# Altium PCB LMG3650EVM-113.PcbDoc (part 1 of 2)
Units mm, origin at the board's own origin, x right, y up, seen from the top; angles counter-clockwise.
Board outline 76.61 x 43.92 mm, 4 copper layers (Top Layer, Signal Layer 1, Signal Layer 2, Bottom Layer), stack 0.688 mm thick; 100 components, 58 nets, 255 pads, 761 vias.
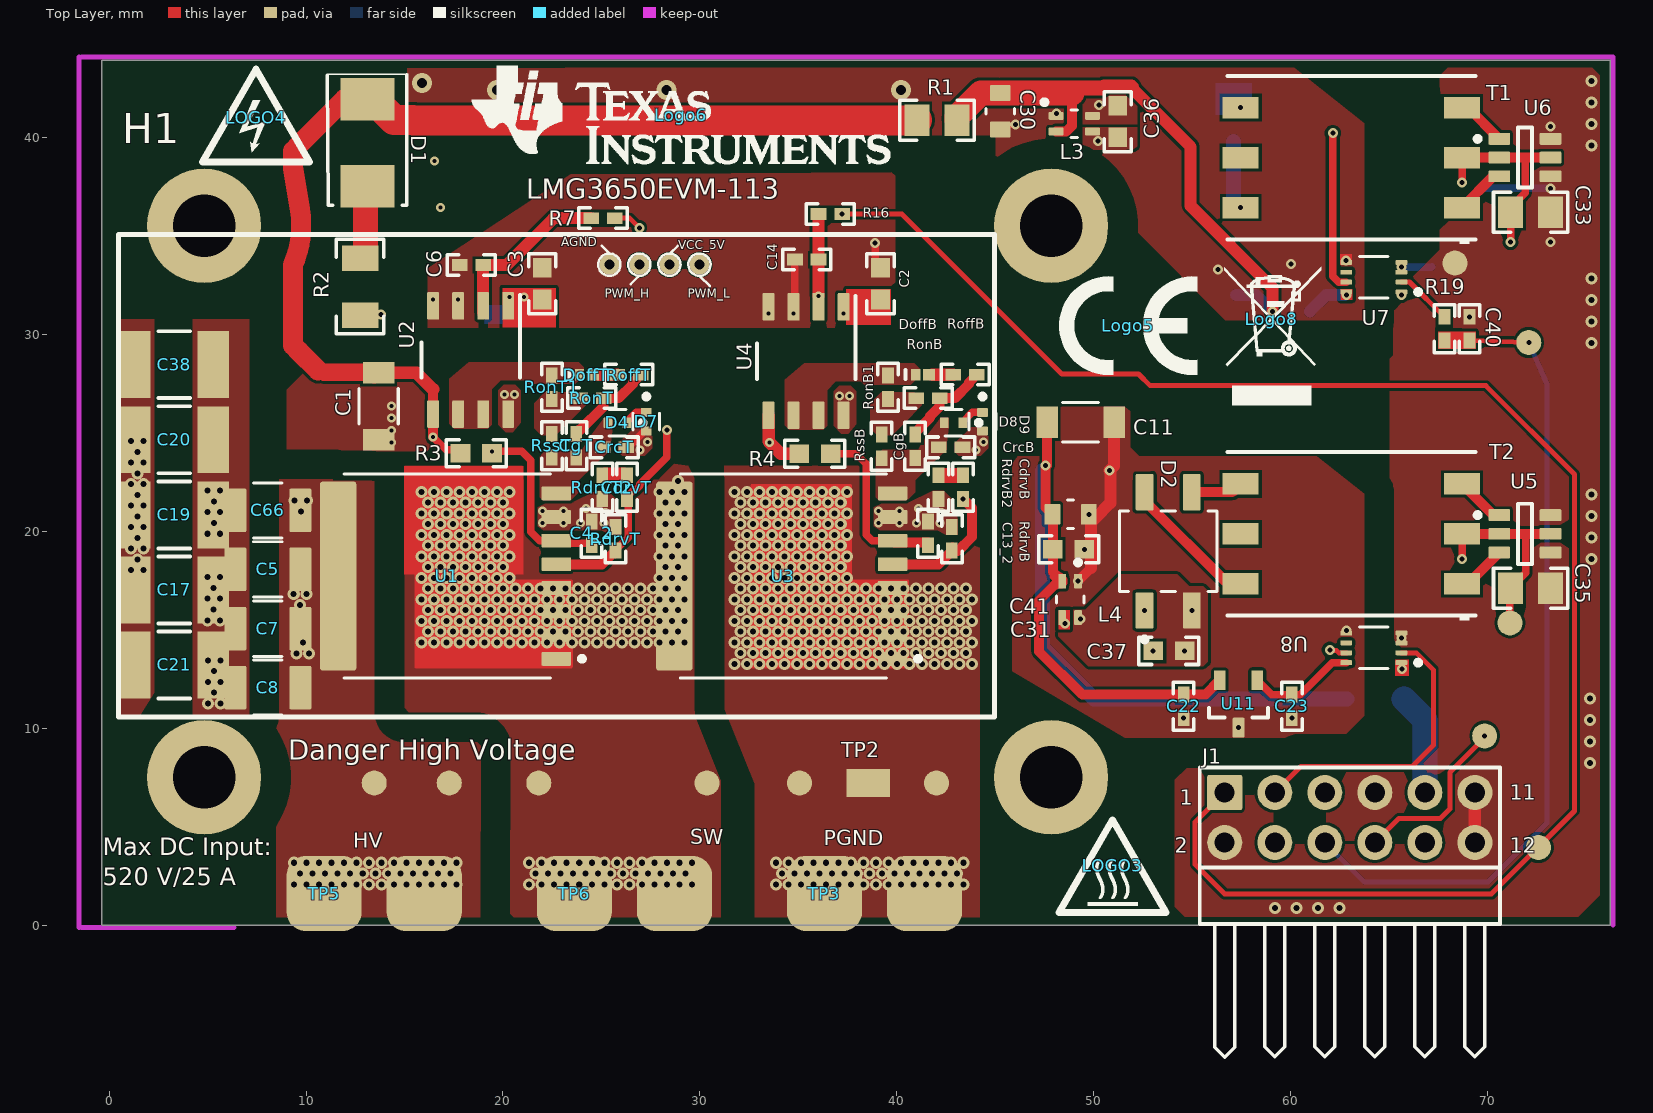
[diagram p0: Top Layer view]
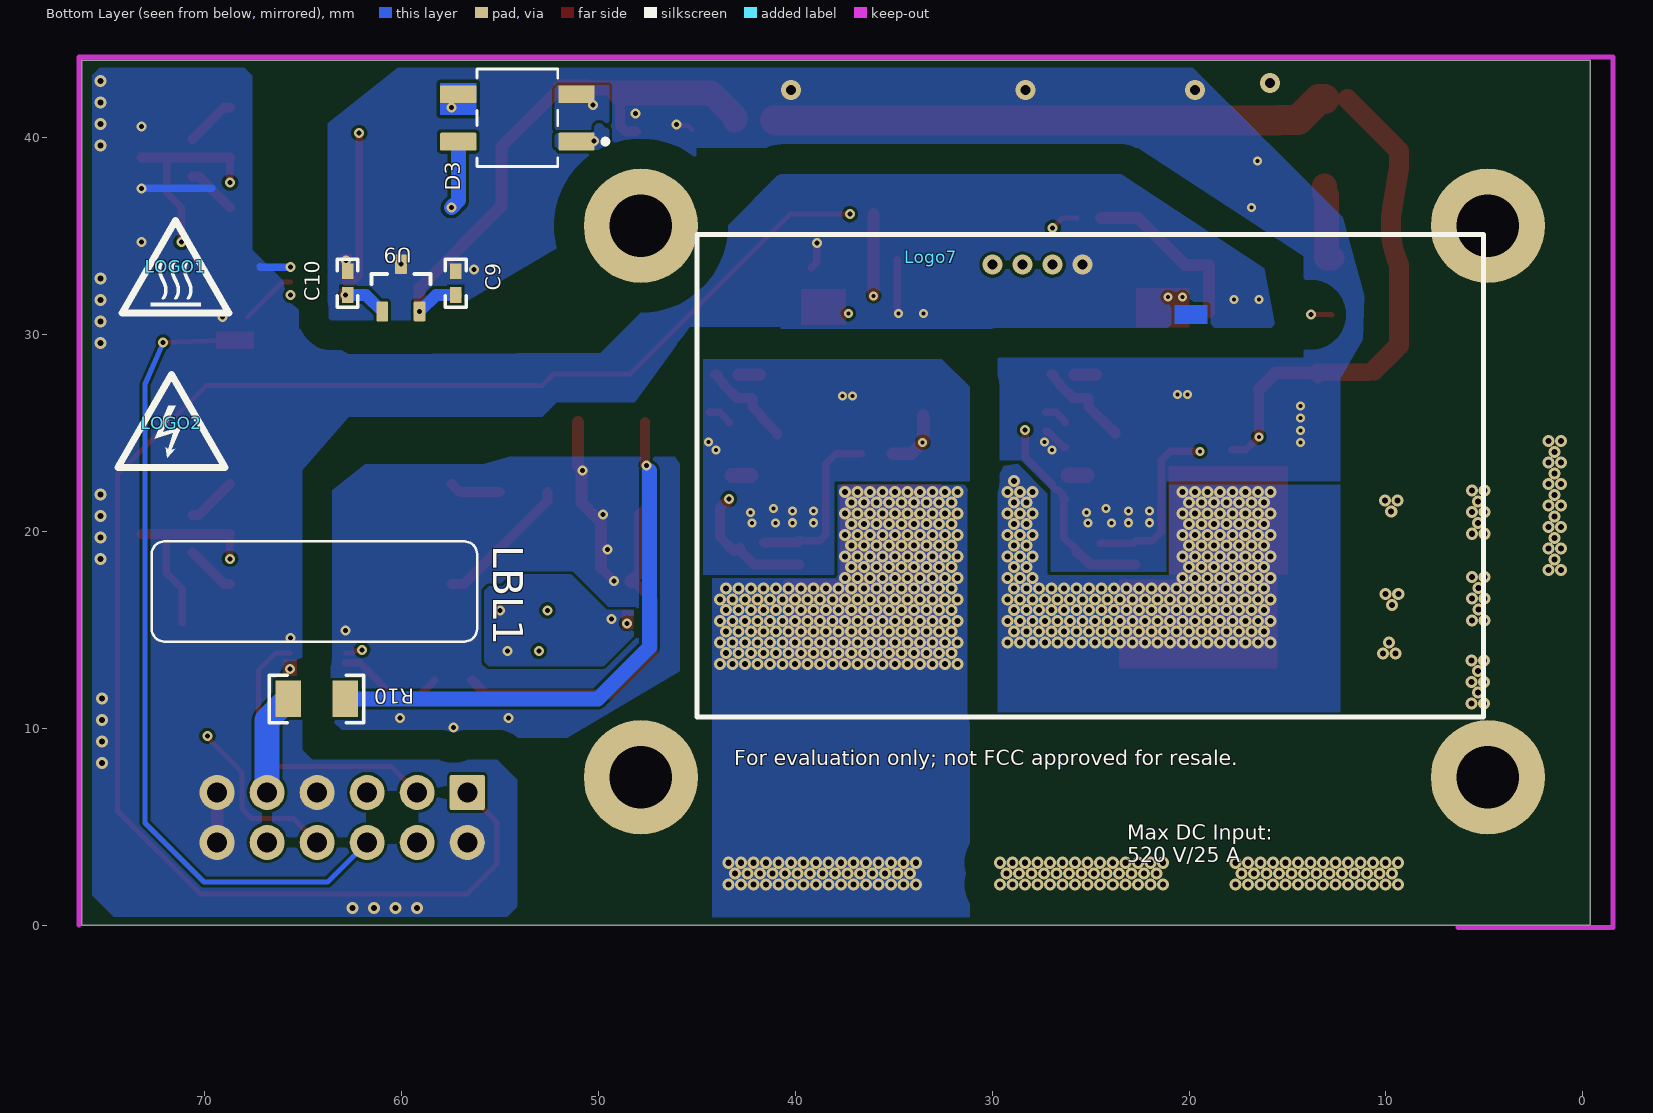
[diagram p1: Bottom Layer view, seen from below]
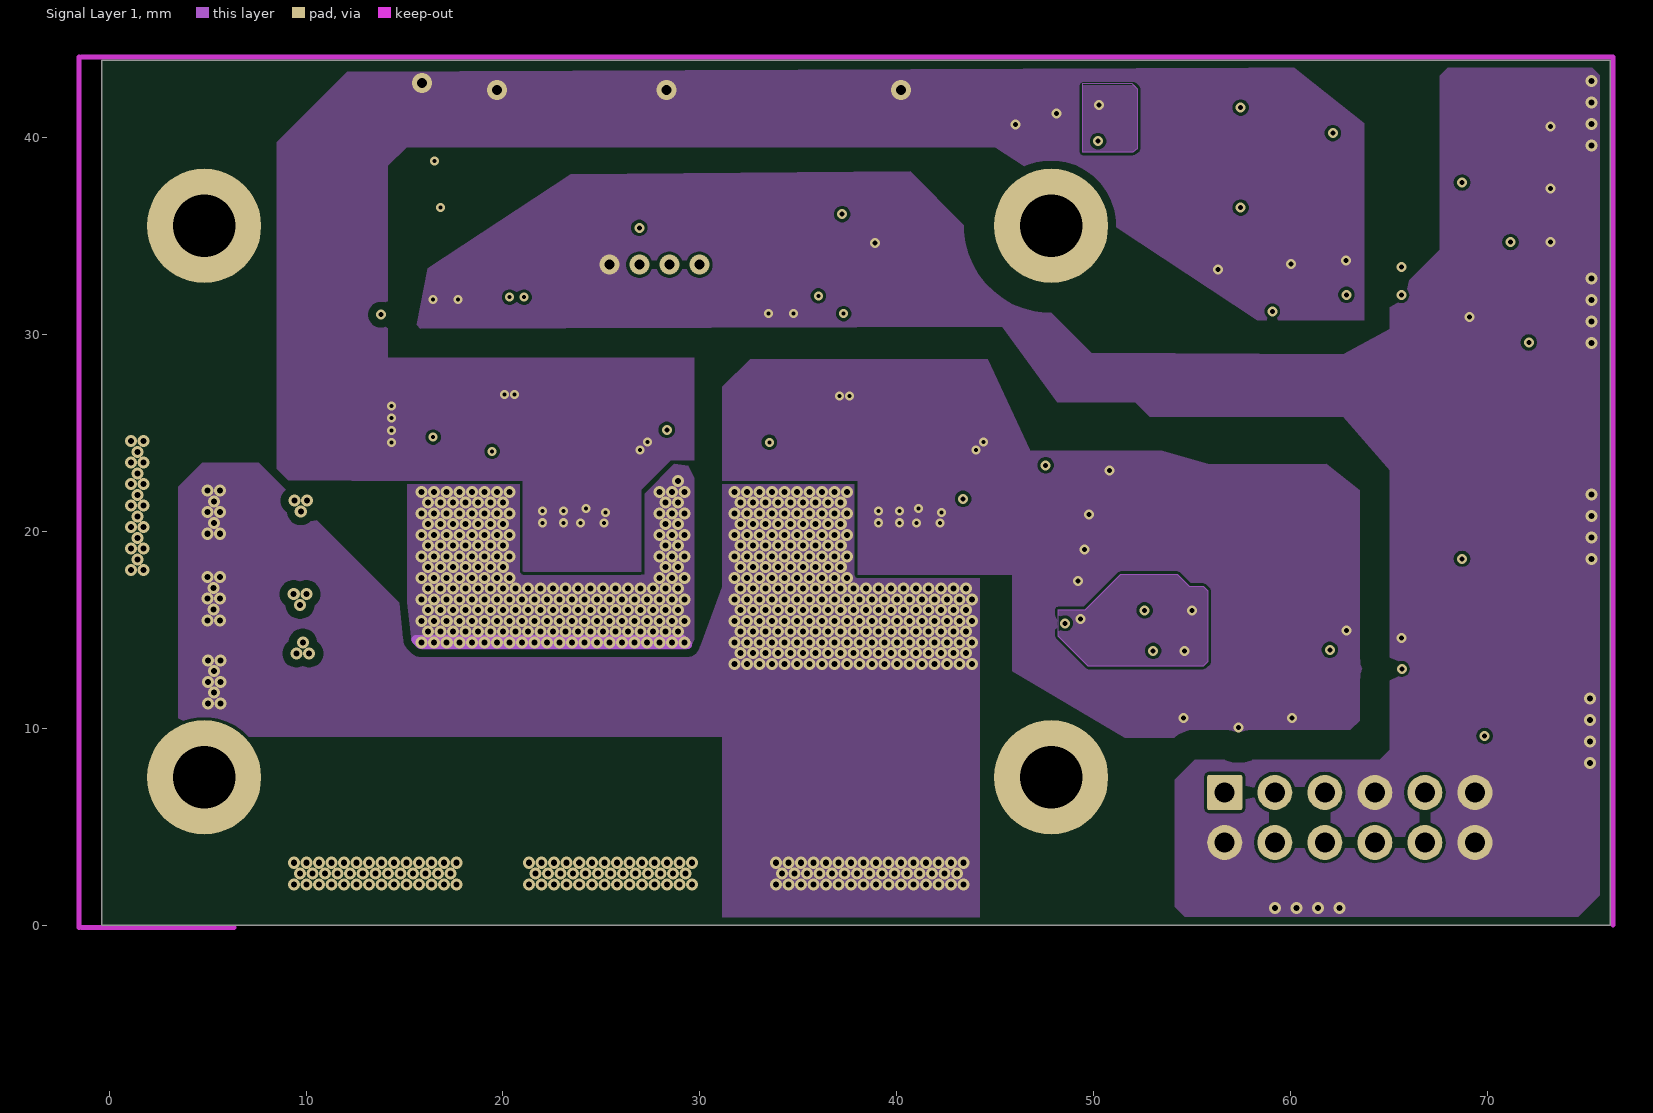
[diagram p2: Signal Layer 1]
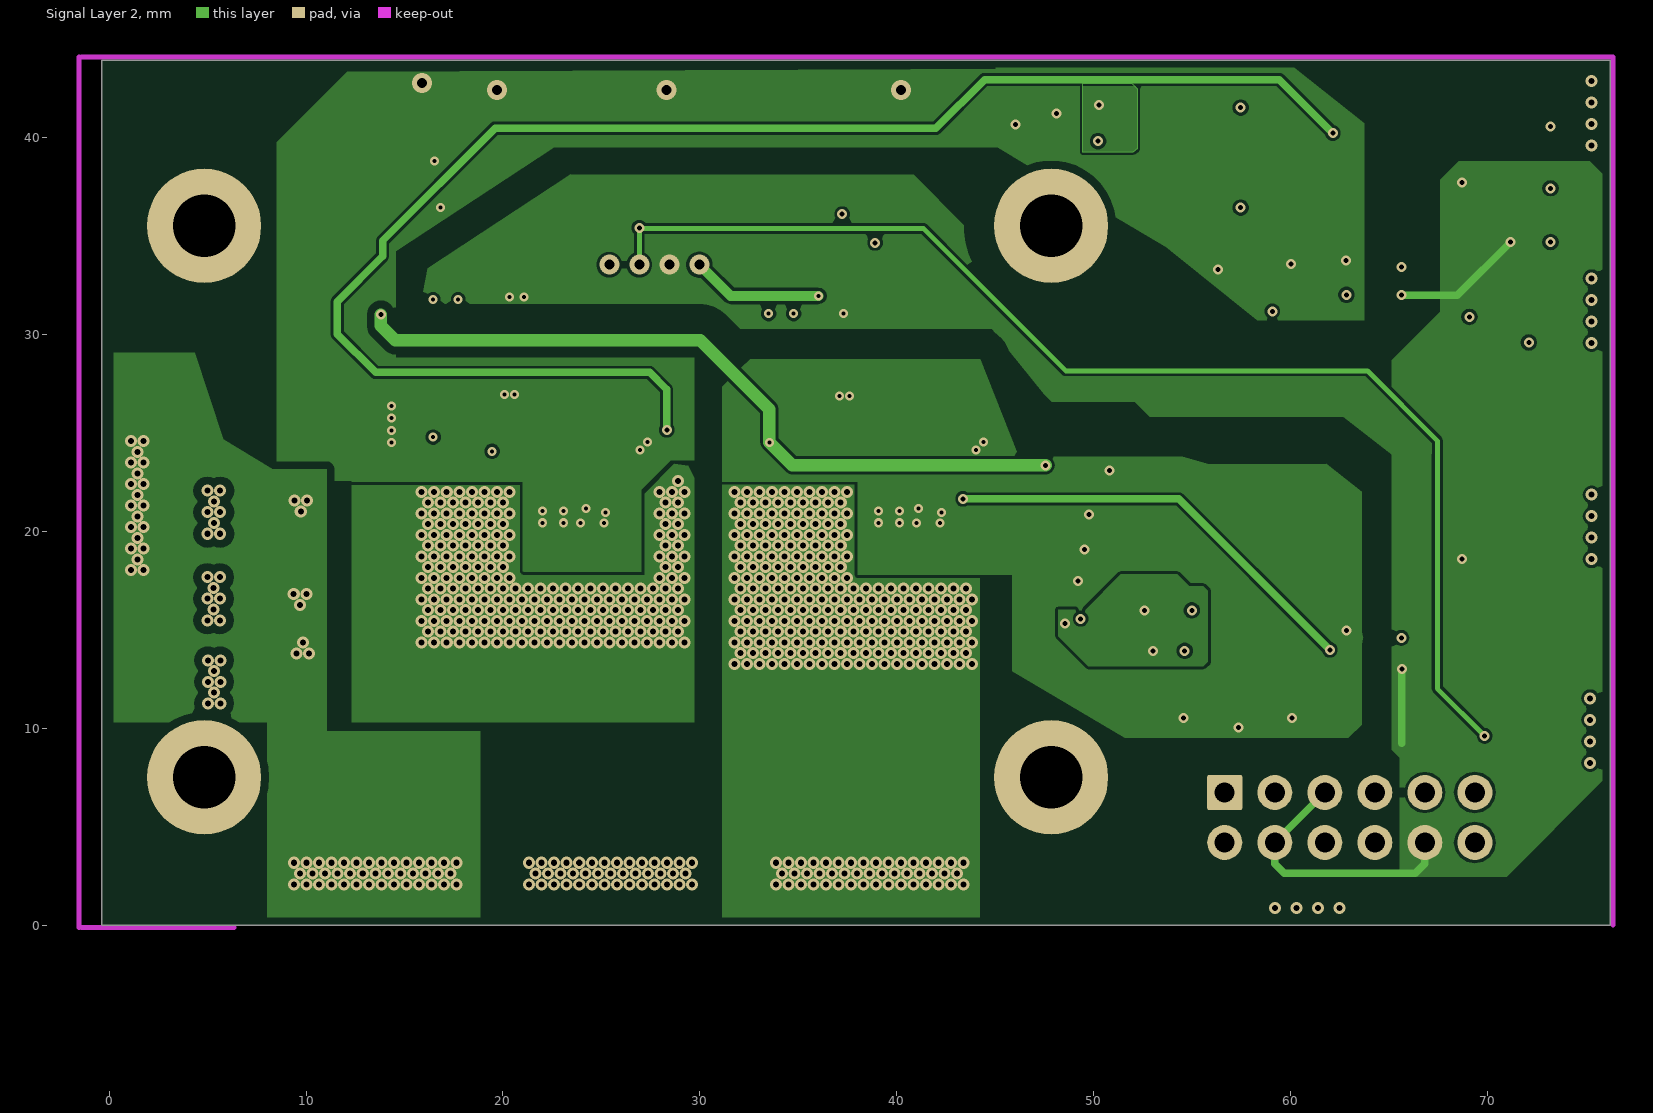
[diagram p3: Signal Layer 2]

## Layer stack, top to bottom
Top Solder: solder mask 0.0102, Solder Resist, Dk 3.5
Top Layer: signal copper 0.0711
Dielectric 1: prepreg 0.1168, FR-4, Dk 4.2
Signal Layer 1: signal copper 0.0711
Dielectric 2: core 0.17, FR-4, Dk 4.2
Signal Layer 2: signal copper 0.0711
Dielectric 3: prepreg 0.1168, FR-4, Dk 4.2
Bottom Layer: signal copper 0.0711
Bottom Solder: solder mask 0.0102, Solder Resist, Dk 3.5

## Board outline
-0.381,0 76.225,0 76.225,43.917 -0.381,43.917

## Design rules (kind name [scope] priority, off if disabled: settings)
AcuteAngle [All] p1: minimum=4.50000000000000E+0001 checktracksonly=FALSE
AssemblyTestPointUsage [All] p1: valid=2
BoardOutlineClearance [OnCopper] p1: gap=0.381 ignorepadtopadclearanceinfootprint=FALSE
Clearance Clearance_U7_6 [InNet('NC') vs InNet('S_SW')] p1: gap=0.152 ignorepadtopadclearanceinfootprint=TRUE
Clearance Clearance_Top_FET_FLT_1 [InNet('Top_FET_FLT') vs InNet('S_SW')] p2: gap=0.152 ignorepadtopadclearanceinfootprint=TRUE
Clearance Clearance_ThermalVias_2 [InNet('NC2')] p3: gap=0.508 ignorepadtopadclearanceinfootprint=TRUE
Clearance "Clearance_Thermal Vias" [InNet('NC5')] p4: gap=0.508 ignorepadtopadclearanceinfootprint=TRUE
Clearance "Clearance_Thermal Vias_1" [InNet('NC6')] p5: gap=0.508 ignorepadtopadclearanceinfootprint=TRUE
Clearance Clearance_VSW_Mid1 [(OnMultiLayer Or OnMid) And InNetClass('VSWNET') vs OnMid And Not InNetClass('VSWNET')] p6: gap=0.406 ignorepadtopadclearanceinfootprint=TRUE
Clearance Clearance_Screw_Top [InNetClass('Screw') vs OnLayer('Top Layer') And Not InNetClass('Screw')] p7: gap=1.524 ignorepadtopadclearanceinfootprint=TRUE
Clearance Clearance_Screw_Bottom [InNetClass('Screw') vs OnLayer('Bottom Layer') And Not InNetClass('Screw')] p8: gap=1.524 ignorepadtopadclearanceinfootprint=TRUE
Clearance Clearance_Screw_Other [InNetClass('Screw') vs Not OnLayer('Top Layer') AND Not InNetClass('Screw')] p9: gap=1.524 ignorepadtopadclearanceinfootprint=TRUE
Clearance Clearance_VSW_Mid2 [(OnMultiLayer Or OnMid) And Not InNetClass('VSWNET') vs OnMid And InNetClass('VSWNET')] p10: gap=0.406 ignorepadtopadclearanceinfootprint=TRUE
Clearance Clearance_VSW [InNetClass('VSWNET') and OnCopper vs Not InNetClass('VSWNET') and OnCopper] p11: gap=1.524 ignorepadtopadclearanceinfootprint=TRUE
Clearance Clearance_VHV_Mid1 [(OnMultiLayer Or OnMid) And InNetClass('VHV') vs OnMid And Not InNetClass('VHV')] p12: gap=0.406 ignorepadtopadclearanceinfootprint=TRUE
Clearance Clearance_VHV_Mid2 [(OnMultiLayer Or OnMid) And Not InNetClass('VHV') vs OnMid And InNetClass('VHV')] p13: gap=0.406 ignorepadtopadclearanceinfootprint=TRUE
Clearance Clearance_VHV [InNetClass('VHV') vs Not InNetClass('VHV')] p14: gap=1.524 ignorepadtopadclearanceinfootprint=TRUE
Clearance Clearance_INGND [InNetClass('INGND') and OnCopper vs Not InNetClass('INGND') and OnCopper] p15: gap=1.524 ignorepadtopadclearanceinfootprint=TRUE
Clearance [All] p16: gap=0.152 ignorepadtopadclearanceinfootprint=TRUE
ComponentClearance ComponentClearance_1 [All] p1: gap=0.025 collisioncheckmode=3 verticalgap=0.254 showdistances=FALSE
ComponentClearance ComponentClearance_Shunt [InComponentClass('Header') vs InComponentClass('Shunt')] p2: gap=0 collisioncheckmode=3 verticalgap=0 showdistances=FALSE
ComponentClearance ComponentClearance_MountingHoles_FiducialMarks [InComponentClass('Mounting Holes') vs InComponentClass('FiducialMark')] p3 off: gap=1.27 collisioncheckmode=3 verticalgap=0.254 showdistances=FALSE
ComponentClearance ComponentClearance_Logo [InComponentClass('Logo')] p4: gap=0 collisioncheckmode=3 verticalgap=0.254 showdistances=FALSE
ComponentClearance ComponentClearance_ScrewToNut [(HasFootprint('NY PMS 440 0025 PH')) vs (HasFootprint('Keystone_1902C'))] p5: gap=0.127 collisioncheckmode=3 verticalgap=0.254 showdistances=FALSE
ComponentClearance ComponentClearance_MountingHoles [InComponentClass('Mounting Holes')] p6: gap=6.35 collisioncheckmode=3 verticalgap=2540 showdistances=FALSE
ComponentClearance ComponentClearance_SmallPassives [HasFootprint('0201*') or HasFootprint('0402*') or HasFootprint('0508') or HasFootprint('0603*') or HasFootprint('0612') or HasFootprint('0805*') or HasFootprint('0815*') or HasFootprint('0830*') or HasFootprint('1206*') or HasFootprint('1210*') or HasFootprint('1808*') or HasFootprint('1812*') or HasFootprint('1825*') or HasFootprint('2010*') or HasFootprint('2220*') or HasFootprint('2225*') or HasFootprint('2512*') or HasFootprint('2728*') or HasFootprint('3518*') vs HasFootprint('0201*') or HasFootprint('0402*') or HasFootprint('0508') or HasFootprint('0603*') or HasFootprint('0612') or HasFootprint('0805*') or HasFootprint('0815*') or HasFootprint('0830*') or HasFootprint('1206*') or HasFootprint('1210*') or HasFootprint('1808*') or HasFootprint('1812*') or HasFootprint('1825*') or HasFootprint('2010*') or HasFootprint('2220*') or HasFootprint('2225*') or HasFootprint('2512*') or HasFootprint('2728*') or HasFootprint('3518*')] p7: gap=0.025 collisioncheckmode=3 verticalgap=0.254 showdistances=FALSE
ComponentClearance ComponentClearance_THtoSMT [IsThruComponent vs IsSMTComponent] p8: gap=0.254 collisioncheckmode=3 verticalgap=0.762 showdistances=FALSE
ComponentClearance ComponentClearance_THtoTH [IsThruComponent vs IsThruComponent] p9: gap=1.88 collisioncheckmode=3 verticalgap=0.762 showdistances=FALSE
ComponentClearance [All] p10: gap=0.025 collisioncheckmode=3 verticalgap=0.254 showdistances=FALSE
DiffPairsRouting [All] p1: maxlimit=2.54 minlimit=0.254 mostfreqgap=0.254 toplayer_minwidth=0.381 toplayer_maxwidth=0.381 toplayer_prefwidth=0.381 midlayer1_minwidth=0.381 midlayer1_maxwidth=0.381 midlayer1_prefwidth=0.381 midlayer2_minwidth=0.381 midlayer2_maxwidth=0.381 midlayer2_prefwidth=0.381 bottomlayer_minwidth=0.381 bottomlayer_maxwidth=0.381 bottomlayer_prefwidth=0.381 maxuncoupledlength=25.4
FabricationTestPointUsage TestPointUsage [All] p1: valid=2 allowmultiple=FALSE
FabricationTestpoint Testpoint [All] p1: side=3 testpointundercomponent=TRUE minsize=1.016 maxsize=2.54 preferedsize=1.524 minholesize=0 maxholesize=1.016 preferedholesize=0.813 testpointgrid=0.025 allowsidetop=TRUE allowsidebottom=TRUE usegrid=TRUE gridtolerance=0
FanoutControl Fanout_LCC [IsLCC] p1: bgadir=Out bgaviamode=Centered fanoutstyle=Auto fanoutdirection=Alternating viagrid=0.025 // Fanout_LCC (Default Rule)
FanoutControl Fanout_BGA [IsBGA] p2: bgadir=Out bgaviamode=Centered fanoutstyle=Auto fanoutdirection=Alternating viagrid=0.025 // Fanout_BGA (Default Rule)
HoleSize [All] p1: absolutevalues=TRUE maxlimit=6.375 minlimit=0.152 maxpercent=80.000 minpercent=20.000
MinimumAnnularRing MinimumAnnularRing_ThermalPadVias [IsVia and InAnyComponent] p1: minimumring=0.114
MinimumAnnularRing [IsVia] p2: minimumring=0.114
MinimumSolderMaskSliver MinimumSolderMaskSliver_Logo [InComponentClass('Logo') vs InComponentClass('Logo')] p1: minsoldermaskwidth=0.018
MinimumSolderMaskSliver [All] p2: minsoldermaskwidth=0.1
PlaneConnect [All] p1: planeconnectstyle=Relief reliefexpansion=0.254 reliefentries=4 reliefconductorwidth=0.254 reliefairgap=0.254
PolygonConnect [All] p1: connectstyle=Direct reliefconductorwidth=0.254 reliefentries=4 polygonreliefangle="90 Angle" airgapwidth=0.254
RoutingVias ThermalPadVias [IsVia and InAnyComponent] p1: holewidth=0.2 width=0.5 viastyle="Through Hole" minholewidth=0.2 minwidth=0.5 maxholewidth=0.33 maxwidth=0.6
RoutingVias [All] p2: holewidth=0.254 width=0.508 viastyle="Through Hole" minholewidth=0.152 minwidth=0.254 maxholewidth=1.016 maxwidth=1.651
SMDToCorner [All] p1: distance=30000
SilkToSilkClearance [All] p1: silktosilkclearance=0
SilkToSolderMaskClearance SilkscreenOverComponentPads [IsPad] p1: minsilkscreentomaskgap=0.127 clearancetoexposedcopper=TRUE
SolderMaskExpansion [All] p1: expansion=0.05 istentingtop=FALSE
SupplyNets "Schematic Supply Nets_15" [InNet('5V')] p1: voltage=0.000
SupplyNets "Schematic Supply Nets_14" [InNet('SW')] p2: voltage=0.000
SupplyNets "Schematic Supply Nets_13" [InNet('S_PGND')] p3: voltage=0.000
SupplyNets "Schematic Supply Nets_12" [InNet('ISO_12V_H')] p4: voltage=0.000
SupplyNets "Schematic Supply Nets_11" [InNet('VGG_H')] p5: voltage=0.000
SupplyNets "Schematic Supply Nets_10" [InNet('PGND')] p6: voltage=0.000
SupplyNets "Schematic Supply Nets_9" [InNet('12V')] p7: voltage=0.000
SupplyNets "Schematic Supply Nets_8" [InNet('5V_B')] p8: voltage=0.000
SupplyNets "Schematic Supply Nets_7" [InNet('ISO_12V_L')] p9: voltage=0.000
SupplyNets "Schematic Supply Nets_6" [InNet('5V_T')] p10: voltage=0.000
SupplyNets "Schematic Supply Nets_5" [InNet('NC')] p11: voltage=0.000
SupplyNets "Schematic Supply Nets_4" [InNet('AGND')] p12: voltage=0.000
SupplyNets "Schematic Supply Nets_3" [InNet('ISO_12V_L_B')] p13: voltage=0.000
SupplyNets "Schematic Supply Nets_2" [InNet('S_SW')] p14: voltage=0.000
SupplyNets "Schematic Supply Nets_1" [InNet('ISO_12V_H_B')] p15: voltage=0.000
SupplyNets "Schematic Supply Nets" [InNet('HVBUS')] p16: voltage=0.000
Width [All] p1: maxlimit=25.4 minlimit=0.152 preferedwidth=0.254 checkconnectedcopper=TRUE
18 further rules are at their usual default settings.

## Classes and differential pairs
component class Logo: Logo6
component class Label: LBL1
component class Header: J1
component class AssemblyNote: ZZ1 ZZ2 ZZ3 ZZ4
net class Screw: NC1 NC2 NC3 NC4
net class PGND: 5V_B 12V Bot_FET_FLT IN_L ISO_12V_L ISO_12V_L_B ISO_RET_L_B ISONC2 NetC13_2_1 NetCdrvB_1 NetCgB_1 NetD1_2 NetD2_3 NetD2_4 NetD8_1 NetDoffB_1 NetDoffB_2 NetRonB1_2 PGND S_PGND
net class INGND: 5V 12V AGND Bot_FET_FAULT Bot_FET_PWM NetR19_1 NetT1_1 NetT1_3 NetT2_1 NetT2_3 PWM_H PWM_L Top_FET_FAULT Top_FET_PWM
component class HVP113A1_Hardware: !PCB1 FID2 H1 H3 H4 H5 H6 LBL1 LOGO1 LOGO2 LOGO3 LOGO4 Logo5 Logo6 Logo7 Logo8 ZZ1 ZZ2 ZZ3 ZZ4
component class HVP113A1_BlankSheet: 33 C1 C2 C3 C4_2 C5 C6 C7 C8 C9 C10 C11 C13_2 C14 C17 C19 C20 C21 C22 C23 C30 C31 C33 C35 C36 C37 C38 C40 C41 C66 CdrvB CdrvT CgB CgT CrcB CrcT D1 D2 D3 D4 D7 D8 D9 DoffB DoffT HV J1 L3 L4 PGND R1 R2 R3 R4 R7 R10 R16 R19 RdrvB RdrvB2 RdrvT RdrvT2 RoffB RoffT RonB RonB1 RonT RonT1 RssB RssT SW T1 T2 TP2 TP3 TP5 TP6 U1 U2 U3 U4 U5 U6 U7 U8 U9 U11
net class VSWNET: 5V_T IN_H ISO_12V_H ISO_12V_H_B ISO_RET_H_B ISONC3 NC NetC4_2_1 NetCdrvT_1 NetCgT_1 NetD3_3 NetD3_4 NetD4_1 NetDoffT_1 NetDoffT_2 NetRonT1_2 S_SW SW Top_FET_FLT VGG_H
net class VHV: HVBUS

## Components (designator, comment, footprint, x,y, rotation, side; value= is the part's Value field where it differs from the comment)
C1 "TMK316AB7106KLHT" 1206_180 13.691,26.338 r270 top value=10uF
C2 "GRM188R70J104KA01D" 0603 39.167,32.563 r90 top value=0.1uF
C3 "GRM188R70J104KA01D" 0603 21.996,32.563 r90 top value=0.1uF
C4_2 "C1005X7R1H104K050BB" 0402 24.506,19.888 r90 top value=0.1uF
C5 "CGA6M1C0G3A682J200AE" FP-CGA6M1C0G3A682J200AE_1210-MFG 8.067,18.061 r0 top value=6.8nF
C6 "C1005C0G1H680J050BA" 0402 18.399,33.51 r180 top value=68pF
C7 "CGA6M1C0G3A682J200AE" FP-CGA6M1C0G3A682J200AE_1210-MFG 8.067,15.045 r0 top value=6.8nF
C8 "CGA6M1C0G3A682J200AE" FP-CGA6M1C0G3A682J200AE_1210-MFG 8.067,12.055 r0 top value=6.8nF
C9 "C1005X7R1H104K050BB" 0402 57.226,32.588 r90 bottom value=0.1uF
C10 "C1005X7R1H104K050BB" 0402 62.713,32.588 r90 bottom value=0.1uF
C11 "TMK316AB7106KLHT" 1206_180 49.327,25.527 r180 top value=10uF
C13_2 "C1005X7R1H104K050BB" 0402 41.573,19.888 r90 top value=0.1uF
C14 "C1005C0G1H680J050BA" 0402 35.422,33.782 r0 top value=68pF
C17 "C1812C303KDGLCAUTO" 1812_254 3.302,17.018 r0 top value=0.03uF
C19 "C1812C303KDGLCAUTO" 1812_254 3.302,20.828 r0 top value=0.03uF
C20 "C1812C303KDGLCAUTO" 1812_254 3.302,24.638 r0 top value=0.03uF
C21 "C1812C303KDGLCAUTO" 1812_254 3.302,13.208 r0 top value=0.03uF
C22 "C1005X7R1H104K050BB" 0402 54.559,11.1 r270 top value=0.1uF
C23 "C1005X7R1H104K050BB" 0402 60.046,11.1 r270 top value=0.1uF
C30 "CGA4J1X7S1E106K125AC" FP-CGA4J1X7S1E106K125AC_0805-MFG 45.243,41.316 r270 top value=10µF
C31 "GRT188C81E475KE13D" 0603 48.717,19.075 r0 top value=4.7uF
C33 "GCM21BR71C475KA73L" 0805_HV 72.166,36.195 r0 top value=4.7uF
C35 "GCM21BR71C475KA73L" 0805_HV 72.166,17.094 r0 top value=4.7uF
C36 "GRT188C81E475KE13D" 0603 51.206,40.792 r90 top value=4.7uF
C37 "GRT188C81E475KE13D" 0603 53.81,13.919 r0 top value=4.7uF
C38 "C1812C303KDGLCAUTO" 1812_254 3.302,28.448 r0 top value=0.03uF
C40 "GCQ1555C1H430JB01D" 0402 69.063,30.277 r90 top value=43pF
C41 "CGA4J1X7S1E106K125AC" FP-CGA4J1X7S1E106K125AC_0805-MFG 48.819,20.853 r0 top value=10µF
C66 "CGA6M1C0G3A682J200AE" FP-CGA6M1C0G3A682J200AE_1210-MFG 8.067,21.051 r0 top value=6.8nF
CdrvB "GCM1555C1H220JA16D" 0402 43.357,22.233 r270 top value=22pF
CdrvT "GCM1555C1H220JA16D" 0402 26.289,22.233 r270 top value=22pF
CgB "GCM1555C1H220JA16D (NC)" 0402 40.926,24.309 r270 top value=22pF
CgT "GCM1555C1H220JA16D (NC)" 0402 23.724,24.333 r270 top value=22pF
CrcB "GCM1555C1H220JA16D" 0402 42.727,24.257 r180 top value=22pF
CrcT "GCM1555C1H220JA16D" 0402 25.659,24.257 r180 top value=22pF
D1 "GB01SLT06-214" SMB 13.114,39.722 r270 top value=650V
D2 "KMB24STR" FP-KMB24STR_SMD4-MFG 53.772,18.974 r90 top
D3 "KMB24STR" FP-KMB24STR_SMD4-MFG 54.099,40.976 r0 bottom
D4 "DZ9F5V6S92-7" FP-CDZVT2R5.1B_SOD-923-MFG 25.811,25.504 r180 top
D7 "DZ9F5V6S92-7" FP-CDZVT2R5.1B_SOD-923-MFG 27.277,25.554 r270 top
D8 "DZ9F5V6S92-7" FP-CDZVT2R5.1B_SOD-923-MFG 42.878,25.504 r180 top
D9 "DZ9F5V6S92-7" FP-CDZVT2R5.1B_SOD-923-MFG 44.345,25.554 r270 top
DoffB "NSR05F30NXT5G" DSN2_0402 41.325,27.94 r0 top value=30V
DoffT "NSR05F30NXT5G" DSN2_0402 24.257,27.94 r0 top value=30V
H1 "S05MZZ14A" S05MZZ14 47.826,35.5 r180 top locked
HV "3621-0-32-15-00-00-08-0" MILL-MAX_3621-0-32-XX-00-00-08-0 16.002,-0.787 r0 top
J1 "TSW-106-08-G-D-RA" AB12-DEST 62.992,5.461 r0 top
L3 "ACM2012-900-2P-T001" FP-ACM2012-900-2P-T001_SMD4-MFG 49.003,40.682 r0 top
L4 "ACM2012-900-2P-T001" FP-ACM2012-900-2P-T001_SMD4-MFG 48.793,16.535 r270 top
LBL1 "THT-14-423-10" Label_650x200 64.402,16.936 r180 bottom
LOGO1 "CAUTION HOT SURFACE" IEC_HotSurface_Small 71.45,33.426 r180 bottom
LOGO2 "DANGER HIGH VOLTAGE" IEC_HighVoltage_Small 71.653,25.476 r180 bottom
LOGO3 "CAUTION HOT SURFACE" IEC_HotSurface_Small 50.947,2.999 r0 top
LOGO4 "DANGER HIGH VOLTAGE" IEC_HighVoltage_Small 7.462,40.977 r0 top
Logo5 "CE Mark" CE_Mark_5mm 51.74,30.429 r0 top
Logo6 "Texas Instruments" TI_Stacked_Overlay_Small 29.043,41.122 r0 top
Logo7 "FCC disclaimer" FCC_disclaimer 33.096,33.909 r180 bottom
Logo8 "WEEE logo" WEEE_Minimum 59.03,30.759 r0 top
PGND "3621-0-32-15-00-00-08-0" MILL-MAX_3621-0-32-XX-00-00-08-0 41.402,-0.787 r0 top
R1 "CRCW08050000Z0EAHP" 0805_HV 42.034,40.87 r180 top value=0
R2 "CRCW12062R05FKEA" 1206 12.749,32.412 r90 top value=2.05
R3 "CRCW06030000Z0EA" 0603 18.644,23.952 r0 top value=0
R4 "CRCW06030000Z0EA" 0603 35.839,23.927 r0 top value=0
R7 "CRCW040249R9FKED" 0402 25.078,35.887 r180 top value=49.9
R10 "ERJ-8GEY0R00V" 1206 64.287,11.481 r180 bottom value=0
R16 "CRCW040249R9FKED" 0402 36.622,36.093 r180 top value=49.9
R19 "CRCW0402300RJNED" 0402 67.793,30.277 r270 top value=300
RdrvB "ERJ-2GEJ203X" 0402 42.784,19.615 r270 top value=20k
RdrvB2 "ERJ-2GEJ203X" 0402 42.11,22.233 r90 top value=20k
RdrvT "ERJ-2GEJ203X" 0402 25.716,19.615 r270 top value=20k
RdrvT2 "ERJ-2GEJ203X" 0402 25.042,22.233 r90 top value=20k
RoffB "CRCW04022R40JNED" 0402 43.458,27.94 r0 top value=2.4
RoffT "CRCW04022R40JNED" 0402 26.391,27.94 r0 top value=2.4
RonB "CRCW04029R10JNED" 0402 41.579,26.746 r0 top value=9.1
RonB1 "CRCW04029R10JNED" 0402 39.547,27.305 r270 top value=9.1
RonT "CRCW04029R10JNED" 0402 24.511,26.746 r0 top value=9.1
RonT1 "CRCW04029R10JNED" 0402 22.479,27.305 r270 top value=9.1
RssB "CRCW04029R10JNED" 0402 39.228,24.303 r270 top value=9.1
RssT "CRCW04029R10JNED" 0402 22.479,24.333 r270 top value=9.1
SW "3621-0-32-15-00-00-08-0" MILL-MAX_3621-0-32-XX-00-00-08-0 28.702,-0.787 r0 top
T1 "750315371" Wurth_750315371 63.068,38.964 r180 top value=105uH
T2 "750315371" Wurth_750315371 63.068,19.863 r180 top value=105uH
TP2 "S2751-46R" Harwin_S2751-46R 38.543,7.214 r0 top
TP3 "3621-0-32-15-00-00-08-0" MILL-MAX_3621-0-32-XX-00-00-08-0 36.322,-0.787 r0 top
TP5 "3621-0-32-15-00-00-08-0" MILL-MAX_3621-0-32-XX-00-00-08-0 10.922,-0.787 r0 top
TP6 "3621-0-32-15-00-00-08-0" MILL-MAX_3621-0-32-XX-00-00-08-0 23.622,-0.787 r0 top
U1 "LMG3650" KLA0009A-NV 17.172,17.715 r180 top
U2 "UCC5350SBDR" D0008B_HV 18.359,28.688 r270 top
U3 "LMG3650" KLA0009A-NV 34.239,17.715 r180 top
U4 "UCC5350SBDR" D0008B_HV 35.387,28.633 r270 top
U5 "SN6505BQDBVTQ1" DBV0006A-MFG 71.882,19.863 r0 top
U6 "SN6505BQDBVTQ1" DBV0006A-MFG 71.882,38.964 r0 top
U7 "ISO6521REU" REU0008A-MFG 64.211,32.893 r180 top
U8 "ISO6521REU" REU0008A-MFG 64.211,14.072 r180 top
U9 "TLV76050DBZR" DBZ0003A_N 60.01,32.353 r90 bottom
U11 "TLV76050DBZR" DBZ0003A_N 57.343,11.227 r270 top
ZZ1 "This Assembly Note is for PCB labels only" AssemblyNoteLabel 6.579,58.979 r0 top
ZZ2 "These assemblies are ESD sensitive, ESD precautions shall be observed." AssemblyNote 6.579,56.515 r0 top
ZZ3 "These assemblies must be clean and free from flux and all contaminants. Use of no clean flux is not acceptable." AssemblyNote 6.579,54.381 r0 top
ZZ4 "These assemblies must comply with workmanship standards IPC-A-610 Class 2, unless otherwise specified." AssemblyNote 6.579,52.324 r0 top

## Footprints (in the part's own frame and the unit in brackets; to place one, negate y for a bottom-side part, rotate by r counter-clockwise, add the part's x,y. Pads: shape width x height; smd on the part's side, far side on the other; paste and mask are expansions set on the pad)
0402 [mm] "0402 from SM-752 data"
  rect 0.8x0.6 smd: 1(-0.6,0) 2(0.6,0)
  silkscreen extent -1.22,-0.52 1.22,0.52, body extent -0.55,-0.3 0.55,0.3, height 0.6
0603 [mm] "0603 from SM-752 data"
  rect 1x0.95 smd: 1(-0.8,0) 2(0.8,0)
  silkscreen extent -1.52,-0.69 1.52,0.69, body extent -0.87,-0.47 0.87,0.47, height 1
0805_HV [mil] "0805 with 30mil clearance between pads"
  rect 50x63 smd: 1(-40,0) 2(40,0)
  silkscreen extent -74,-40 74,40, body extent -43,-29 43,29, height 57
1206 [mm] "1206 from SM-752 data"
  rect 1.3x1.85 smd: 1(-1.45,0) 2(1.45,0)
  silkscreen extent -2.4,-1.21 2.4,1.21, body extent -1.7,-0.9 1.7,0.9, height 1.35
1206_180 [mm] "1206_180"
  rect 1.1x1.6 smd: 1(-1.7,0) 2(1.7,0)
  silkscreen extent -0.9,-1 0.9,1, body extent -1.75,-0.95 1.75,0.95, height 1.8
1812_254 [mm] "SMD, 2-Leads, Body 4.8x3.4mm"
  rect 1.6x3.4 smd: 1(-2,0) 2(2,0)
  silkscreen extent -0.8,-1.7 0.8,1.7, body extent -2.4,-1.7 2.4,1.7, height 2.54
AB12-DEST [mil] "Samtec right angle header, pins flipped from convention"
  rrect10% 70x70 hole 40: 1(-250,50)
  round 70 hole 40: 2(-250,-50) 3(-150,50) 4(-150,-50) 5(-50,50) 6(-50,-50) 7(50,50) 8(50,-50) 9(150,50) 10(150,-50) 11(250,50) 12(250,-50)
  silkscreen extent -300,-479 300,100, body extent -300,-440 300,63, height 219
AssemblyNote [mm] "Assembly Note"
AssemblyNoteLabel [mm] "Assembly Note for PCB Labels"
CE_Mark_5mm [mm] "Minimum text height for CE Mark"
  silkscreen extent -3.5,-2.5 3.5,2.5
D0008B_HV [mm] "SOIC, 8-Leads, Body 4.9x3.9mm, Pitch 1.27mm, HV / Isolation option"
  rrect17% 1.4x0.6 smd: 1(-2.75,1.905) 2(-2.75,0.635) 3(-2.75,-0.635) 4(-2.75,-1.905) 5(2.75,-1.905) 6(2.75,-0.635) 7(2.75,0.635) 8(2.75,1.905)
  silkscreen extent -3.3,-2.5 0.9,2.5, body extent -3,-2.45 3,2.45, height 1.63
DBV0006A-MFG [mm]
  rrect17% 1.1x0.6 smd paste+0 mask+0: 1(-1.3,0.95) 2(-1.3,0) 3(-1.3,-0.95) 4(1.3,-0.95) 5(1.3,0) 6(1.3,0.95)
  silkscreen extent -2.52,-1.53 0.35,1.53, body extent -1.95,-1.78 1.95,1.78, height 0.25
DBZ0003A_N [mm] "SOT23, 3-Leads, Body 2.9x1.3mm, Pitch 0.95mm, Lead Span 2.4mm, IPC Medium Density"
  rrect17% 1x0.6 smd: 1(-1.2,0.95) 2(-1.2,-0.95) 3(1.2,0)
  silkscreen extent 0.2,-1.5 0.7,1.5, body extent -1.26,-1.46 1.26,1.46, height 0.98
DSN2_0402 [mm] "ON SEMICONDUCTOR"
  rect 0.47x0.6 smd: 1(-0.367,0)
  rect 0.6x0.6 smd: 2(0.308,0)
  silkscreen extent -0.89,-0.22 -0.89,0.25, body extent -0.5,-0.3 0.5,0.3, height 0.32
FCC_disclaimer [mm]
FP-ACM2012-900-2P-T001_SMD4-MFG [mm]
  rrect25% 0.75x0.4 smd paste+0 mask+0: 1(-0.925,0.4) 2(-0.925,-0.4) 3(0.925,-0.4) 4(0.925,0.4)
  silkscreen extent -1.64,-0.7 0.18,1.22, body extent -1.4,-0.8 1.4,0.8, height 0.25
FP-CDZVT2R5.1B_SOD-923-MFG [mm]
  rrect22% 0.45x0.55 smd paste+0 mask+0: 1(-0.475,0) 2(0.475,0)
  silkscreen extent -1.4,-0.67 0.43,0.67, body extent -0.8,-0.43 0.8,0.43, height 0.25
FP-CGA4J1X7S1E106K125AC_0805-MFG [mm]
  rrect13% 0.8x1.05 smd paste+0 mask+0: 1(-0.925,0) 2(0.925,0)
  silkscreen extent -0.15,-0.72 0.15,0.72, body extent -1.43,-0.82 1.43,0.82, height 0.25
FP-CGA6M1C0G3A682J200AE_1210-MFG [mm]
  rrect9% 1.1x2.2 smd paste+0 mask+0: 1(-1.65,0) 2(1.65,0)
  silkscreen extent -0.72,-1.4 0.72,1.4, body extent -1.6,-1.25 1.6,1.25, height 2.81
FP-KMB24STR_SMD4-MFG [mm]
  rrect11% 1.84x0.9 smd paste+0 mask+0: 1(-3,1.2) 2(-3,-1.2) 3(3,-1.2) 4(3,1.2)
  silkscreen extent -4.59,-2.47 2.05,2.47, body extent -4.02,-2.58 4.02,2.58, height 0.25
Harwin_S2751-46R [mm] "Test Point, SMT"
  rect 2.2x1.4 smd: 1(0,0)
  body extent -1,-0.6 1,0.6, height 1.4
IEC_HighVoltage_Small [mm]
  silkscreen extent -2.72,-2.24 2.72,2.47
IEC_HotSurface_Small [mm]
  silkscreen extent -2.72,-2.36 2.72,2.35
KLA0009A-NV [mm]
  rrect14% 1.5x0.7 smd paste+0 mask-1000: 1(-5.539,4.2) 2(-5.539,3) 3(-5.539,1.8) 4(-5.539,0.6) 5(-5.539,-0.6) 6(-5.539,-1.8) 7(-5.539,-3) 8(-5.539,-4.2)
  rrect15% 1.843x9.6 smd paste-1000 mask-1000: 9(5.539,0)
  Top Layer region: -6.36,4.6 -6.351,4.635 -6.325,4.661 -6.29,4.67 -6.29,4.67 1.587,4.67 1.622,4.661 1.648,4.635 1.657,4.6 1.657,4.6 1.657,-4.6 1.648,-4.635 1.622,-4.661 1.587,-4.67 1.587,-4.67 -3.388,-4.67 -3.423,-4.661 -3.449,-4.635 -3.458,-4.6 -3.458,-4.6 -3.458,0.13 -3.462,0.149 -3.473,0.165 -3.489,0.176 -3.508,0.18 -3.508,0.18 -6.29,0.18 -6.317,0.185 -6.339,0.201 -6.355,0.223 -6.36,0.25 -6.36,0.25
  silkscreen extent -6.96,-5.18 5.24,5.18, body extent -6.46,-5.1 6.56,5.1, height 0.25
Label_650x200 [mil] "Thermal Transfer Label"
  round 1 on Mech14: 0(0,0)
  silkscreen extent -325,-100 325,100, body extent -325,-100 325,100, height 1
MILL-MAX_3621-0-32-XX-00-00-08-0 [mil]
  rrect50% 150x150 smd: 1(0,94)
  body extent -62,-199 63,157, height 62
REU0008A-MFG [mm]
  rrect40% 0.6x0.25 smd paste+0 mask+0: 1(-1.4,0.75) 2(-1.4,0.25) 3(-1.4,-0.25) 4(-1.4,-0.75) 5(1.4,-0.75) 6(1.4,-0.25) 7(1.4,0.25) 8(1.4,0.75)
  silkscreen extent -2.38,-1.05 0.72,1.05, body extent -1.8,-1.15 1.8,1.15, height 0.25
S05MZZ14 [mm]
  round 5.8 hole 3.175: 1(0,28) 1(0,0) 1(43,28) 1(43,0)
  body extent -3.42,-3.33 46.31,31.37
SMB [mm] "Molded Diode, 2-Leads, Body 5.4x3.6mm, IPC Medium Density, based on OnSemi component dimensions"
  rect 2.159x2.743 smd: 1(-2.21,0) 2(2.21,0)
  silkscreen extent -3.52,-2.08 3.18,2.08, body extent -2.7,-1.8 2.7,1.8, height 2.32
TI_Stacked_Overlay_Small [mm]
  silkscreen extent -10.63,-2.49 10.63,2.49
WEEE_Minimum [mm] "WEEElie bin"
  silkscreen extent -2.42,-4.38 2.52,2.65
Wurth_750315371 [mm] "SMD, Body 12.6x8.3mm, Pitch 2.54mm"
  rect 1.83x1.09 smd: 1(-5.62,2.54) 2(-5.62,0) 3(-5.62,-2.54) 4(5.62,-2.54) 5(5.62,0) 6(5.62,2.54)
  silkscreen extent -6.3,-4.15 6.3,4.4, body extent -6.35,-4.2 6.35,4.2, height 4.11

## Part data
C1 C11: library part CMP-0750154-1, "CAP, CERM, 10 µF, 25 V,+/- 10%, X7R, AEC-Q200 Grade 1, 1206", Cap_Case=1206, Manufacturer="Taiyo Yuden", TempCo=X7R, Tolerance_%=10%, Value2=25V, ValueDisplayed=10µF
C2 C3: library part CMP-0007359-4, "CAP, CERM, 0.1 uF, 6.3 V, +/- 10%, X7R, 0603", Cap_Case=0603, Manufacturer=MuRata, Supplier Part Number 1=GRM188R70J104KA01D-ND, TempCo=X7R, Tolerance_%=10%, Value1=Unknown, Value2=6.3V, ValueDisplayed=0.1uF
C4_2 C9 C10 C13_2 C22 C23: library part CMP-0006297-2, "CAP, CERM, 0.1 uF, 50 V, +/- 10%, X7R, 0402", Cap_Case=0402, Manufacturer=TDK, Supplier Part Number 1=445-5932-1-ND, TempCo=X7R, Tolerance_%=10%, Value1="0.039064 ohm", Value2=50V, ValueDisplayed=0.1uF
C5 C7 C8 C66: library part CMP-0092736-1, "Cap Ceramic 6.8nF 1000V C0G 5% Pad SMD 1210 +125°C Automotive T/R", Manufacturer=TDK, Operating Temperature Range="-55°C to +125°C", TempCo=30ppm/°C, Temperature Characteristic=C0G, Tolerance_%=0.05%, ValueDisplayed=6.8nF
C6 C14: library part CMP-0006251-2, "CAP, CERM, 68 pF, 50 V, +/- 5%, C0G/NP0, 0402", Alternate Manufacturer=Murata, Alternate PartNumber=GRM1555C1H680JA01D, Cap_Case=0402, Manufacturer=TDK, Supplier Part Number 1=445-1245-1-ND, TempCo=C0G/NP0, Tolerance_%=5%, Value1=Unknown, Value2=50V, ValueDisplayed=68pF
C17 C19 C20 C21 C38: library part CMP-0009326-2, "0.03 µF ±10% 1000V (1kV) Ceramic Capacitor C0G, NP0 1812 (4532 Metric)", Cap_Case=1812, Manufacturer=Kemet, Supplier Part Number 1=399-C1812C303KDGLCAUTOTR-ND, TempCo=NP0, Tolerance_%=10%, Value1=Unknown, Value2=1000V, ValueDisplayed=0.03uF
C30 C41: library part CMP-0091069-1, "Cap Ceramic 10uF 25V X7S 10% Pad SMD 0805 +125°C Automotive T/R", Manufacturer="TDK Corporation", Operating Temperature Range="-55°C to +125°C", TempCo=22%, Temperature Characteristic=X7S, Tolerance_%=0.1%, ValueDisplayed=10uF
C31 C36 C37: library part CMP-0085645-1, "CAP, CERM, 4.7 µF, 25 V,+/- 10%, X6S, AEC-Q200 Grade 2, 0603", Cap_Case=0603, Manufacturer=MuRata, TempCo=X6S, Tolerance_%=10%, Value2=25V, ValueDisplayed=4.7µF
C33 C35: library part CMP-0008020-2, "CAP, CERM, 4.7 uF, 16 V, +/- 10%, X7R, AEC-Q200 Grade 1, 0805", Cap_Case=0805, Manufacturer=MuRata, Supplier Part Number 1=490-5332-1-ND, TempCo=X7R, Tolerance_%=10%, Value1=Unknown, Value2=16V, ValueDisplayed=4.7uF
C40: library part CMP-0860835-1, "CAP, CERM, 43 pF, 50 V,+/- 5%, C0G/NP0, AEC-Q200 Grade 1, 0402", Cap_Case=0402, Manufacturer=MuRata, TempCo=C0G/NP0, Tolerance_%=5%, Value2=50V, ValueDisplayed=43pF
CdrvB CdrvT CrcB CrcT: library part CMP-0006348-2, "CAP, CERM, 22 pF, 50 V, +/- 5%, C0G/NP0, AEC-Q200 Grade 1, 0402", Cap_Case=0402, Manufacturer=MuRata, Supplier Part Number 1=490-9648-1-ND, TempCo=C0G/NP0, Tolerance_%=5%, Value1=Unknown, Value2=50V, ValueDisplayed=22pF
CgB CgT: library part CMP-0006348-2, "CAP, CERM, 22 pF, 50 V, +/- 5%, C0G/NP0, AEC-Q200 Grade 1, 0402", Cap_Case=0402, Manufacturer=MuRata, PartNumber=GCM1555C1H220JA16D, Supplier Part Number 1=490-9648-1-ND, TempCo=C0G/NP0, Tolerance_%=5%, Value1=Unknown, Value2=50V, ValueDisplayed=22pF
D1: library part CMP-0076998-2, "Diode, Schottky, 650 V, 1 A, SMB", Manufacturer="GeneSiC Semiconductor", Value1=1A, Value2=2V
D2 D3: library part CMP-0090590-2, "Bridge Rectifier Single Phase Schottky 40V Surface Mount MBS", Digikey Part Number=1655-1884-1-ND, Forward Current=2A, Manufacturer="SMC Diode Solutions", Max Surge Forward Current=50A, Operating Temperature Range="-55°C to +150°C", Peak Reverse Current=0.1mA, ValueDisplayed=28pF
D4 D7 D8 D9: library part CMP-0123139-1, "DIODE ZENER 5.6V 200MW SOD923", Digikey Part Number=CDZVT2R5.1BCT-ND, Manufacturer=ROHM, Max Reverse Leakage Current=2uA, Mouser Part Number=755-CDZVT2R5.1B, Operating Temperature Range="to +150°C", Part Number=CDZVT2R5.1B, Power_W=100mW
DoffB DoffT: library part CMP-0077002-2, "Diode, Schottky, 30 V, 0.5 A, 0402 Diode", Manufacturer="ON Semiconductor", Value1=0.5A, Value2=0.43V
H1: library part HeatSink_NoPins, "Heat Sink, Black Anodized, 35 x 50 mm,  20 mm high, with Push Pin and Spring", Manufacturer="Alpha Novatech", PartNumber=S05MZZ13
HV PGND SW TP3 TP5 TP6: library part CMP-0082316-1, Manufacturer=Mill-Max, Supplier Part Number 1=575-3621032150000
J1: library part CMP-0075414-2, "Header, 100mil, 6x2, Gold, R/A, TH", Color=Black, Current_A=6.3A, Manufacturer=Samtec, Supplier Part Number 1=SAM1037-06-ND, Voltage_V=550V
L3 L4: library part CMP-0090488-1, "2 Line Common Mode Choke Surface Mount 90 Ohms @ 100MHz 400mA DCR 190mOhm", Digikey Part Number=445-15969-1-ND, Impedance At Frequency="90Ω @ 100MHz", Manufacturer=TDK, Mouser Part Number=810-ACM20129002PT001, Operating Temperature Range="-40°C to +105°C"
LBL1: library part CMP-0003625-1, "Thermal Transfer Printable Labels, 0.650\" W x 0.200\" H - 10,000 per roll", Manufacturer=Brady, Supplier Part Number 1=97C5133
LOGO1 LOGO3: library part CMP-0074837-1, "IEC 61010-1 Hot Surface Warning"
LOGO2 LOGO4: library part CMP-0074835-1, "IEC 61010-1 High Voltage Warning"
Logo5: library part CMP-0074844-1
Logo6: library part CMP-0074838-1, "Texas Instrument Corporate Signature"
Logo7: library part CMP-0074847-1, "FCC_disclaimer"
Logo8: library part CMP-0074769-1
R1: library part CMP-0020443-3, "RES, 0, 5%, 0.333 W, AEC-Q200 Grade 0, 0805", Manufacturer=Vishay-Dale, Power_W=333mW, Supplier Part Number 1=541-0.0TBCT-ND, TempCo="200 ppm/C", Tolerance_%=5%, Value2=0.333W, Value_Code=0000, ValueDisplayed=0
R2: library part CMP-0016879-3, "RES, 2.05, 1%, 0.25 W, AEC-Q200 Grade 0, 1206", Manufacturer=Vishay-Dale, Power_W=250mW, Supplier Part Number 1=541-2.05FFCT-ND, TempCo="100 ppm/C", Tolerance_%=1%, Value2=0.25W, Value_Code=2R05, ValueDisplayed=2.05
R3 R4: library part CMP-0025697-4, "RES, 0, 5%, 0.1 W, AEC-Q200 Grade 0, 0603", Manufacturer=Vishay-Dale, Power_W=100mW, Supplier Part Number 1=541-0.0GCT-ND, TempCo="200 ppm/C", Tolerance_%=5%, Value2=0.1W, Value_Code=0000, ValueDisplayed=0
R7 R16: library part CMP-0026404-2, "RES, 49.9, 1%, 0.063 W, AEC-Q200 Grade 0, 0402", Manufacturer=Vishay-Dale, Power_W=63mW, Supplier Part Number 1=541-49.9LCT-ND, TempCo="100 ppm/C", Tolerance_%=1%, Value2=0.063W, Value_Code=49R9, ValueDisplayed=49.9
R10: library part CMP-0018748-3, "RES, 0, 5%, 0.25 W, AEC-Q200 Grade 0, 1206", Manufacturer=Panasonic, Power_W=250mW, Supplier Part Number 1=P0.0ECT-ND, TempCo="600 ppm/C", Tolerance_%=5%, Value2=0.25W, Value_Code=0000, ValueDisplayed=0
R19: library part CMP-0026902-3, "RES, 300, 5%, 0.063 W, AEC-Q200 Grade 0, 0402", Manufacturer=Vishay-Dale, Power_W=63mW, Supplier Part Number 1=541-300JCT-ND, TempCo="200 ppm/C", Tolerance_%=5%, Value2=0.063W, Value_Code=300R, ValueDisplayed=300
RdrvB RdrvB2 RdrvT RdrvT2: library part CMP-0026996-1, "RES, 20 k, 5%, 0.1 W, AEC-Q200 Grade 0, 0402", Manufacturer=Panasonic, Power_W=100mW, Supplier Part Number 1=P20KJCT-ND, TempCo="200 ppm/C", Tolerance_%=5%, Value2=0.1W, Value_Code=20k0, ValueDisplayed=0
RoffB RoffT: library part CMP-0026899-2, "RES, 2.4, 5%, 0.063 W, 0402", Manufacturer=Vishay-Dale, Power_W=63mW, Supplier Part Number 1=541-2.4JCT-ND, TempCo="200 ppm/C", Tolerance_%=5%, Value2=0.063W, Value_Code=2R40
RonB RonB1 RonT RonT1 RssB RssT: library part CMP-0026991-4, "RES, 9.1, 5%, 0.063 W, AEC-Q200 Grade 0, 0402", Manufacturer=Vishay-Dale, Power_W=63mW, Supplier Part Number 1=541-9.1JCT-ND, TempCo="200 ppm/C", Tolerance_%=5%, Value2=0.063W, Value_Code=9R10
T1 T2: library part CMP-0030623-1, "Transformer, 105uH, TH", Manufacturer="Wurth Elektronik", ValueDisplayed=105uH
TP2: library part CMP-0003968-1, "Test Point, SMT", Manufacturer=Harwin, Supplier Part Number 1=952-2664-1-ND
U1 U3: library part CMP-0120607-2, Manufacturer="Texas Instruments", Operating Temperature Range=to, Part Number=LMG365x
U2 U4: library part CMP-0077706-1, "3-kVRMS Single-Channel Isolated Gate Drivers, D0008B (SOIC-8)", Alternate Manufacturer="Texas Instruments", Alternate PartNumber=UCC5350SBD
U5 U6: library part CMP-0089033-2, "Transformer Driver PMIC SOT-23-6", Manufacturer="Texas Instruments", Operating Temperature Range="-40°C to +125°C"
U7 U8: library part CMP-0035039-1, "General Purpose Dual-Channel Functional Isolators", Manufacturer="Texas Instruments", Max Supply Voltage=5.5V, Min Supply Voltage=1.71V, Nominal Supply Current=1.2-5.2mA, Operating Temperature Range="-40°C to +125°C"
U9 U11: library part CMP-0074892-1, "100-mA, 30-V, Fixed-Output, Linear-Voltage Regulator, DBZ0003A (SOT-23-3)", Alternate Manufacturer="Texas Instruments", Alternate PartNumber=TLV76050DBZT
ZZ1: library part CMP-0003616-3
ZZ2: library part CMP-0077236-1
ZZ3: library part CMP-0077237-1
ZZ4: library part CMP-0077238-1

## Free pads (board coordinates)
  round 1.27 smd paste-0.762: 1(13.462,7.214) 1(17.272,7.214) 1(21.819,7.214) 1(30.353,7.214) 1(35.052,7.214) 1(42.012,7.214) 1(68.326,33.604) 1(69.837,9.601) 1(71.12,15.342) 1(72.078,29.575) 1(72.568,3.937)

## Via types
v1: diameter 0.61, hole 0.305, Top Layer to Bottom Layer, tented both sides, 665 vias
v2: diameter 0.508, hole 0.254, Top Layer to Bottom Layer, tented both sides, 47 vias
v3: diameter 0.457, hole 0.203, Top Layer to Bottom Layer, tented both sides, 41 vias
v4: diameter 1.016, hole 0.508, Top Layer to Bottom Layer, 8 vias

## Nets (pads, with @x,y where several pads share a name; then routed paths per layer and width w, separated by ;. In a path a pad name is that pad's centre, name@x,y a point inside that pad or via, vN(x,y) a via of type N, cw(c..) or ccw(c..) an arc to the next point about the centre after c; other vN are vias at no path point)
5V: C2.1 C3.1 C33.1 C35.1 J1.4 J1.5 J1.10 pad.1@71.12,15.342 T1.2 T2.2 U2.1 U4.1 U5.2 U5.5 U6.2 U6.5 U7.1 U8.1 | length 45.2
  Top Layer w0.381: v3(37.292,31.047) U4.1@37.292,31.102 ; v2(68.688,18.593) T2.2@68.688,19.863 ; v2(68.688,37.694) T1.2@68.688,38.964 ; pad.1@71.12,15.342 71.12,17.064 C35.1@71.15,17.094 71.933,17.877 71.933,19.863 ; v2(71.15,34.671) C33.1@71.15,36.195 71.15,36.428 71.907,37.186 71.907,38.964
  Top Layer w0.508: T2.2@68.688,19.863 U5.2@70.582,19.863 71.933,19.863 U5.5@73.182,19.863 ; T1.2@68.688,38.964 U6.2@70.582,38.964 71.907,38.964 U6.5@73.182,38.964
  Signal Layer 2 w0.381: J1.5@61.722,6.731 J1.4@59.182,4.191 59.182,3.111 59.652,2.642 66.319,2.642 66.802,3.124 J1.10@66.802,4.191 ; v2(65.608,31.979) 68.458,31.979 v2(71.15,34.671) ; 65.634,9.22 v2(65.634,13.005)
  other v3: 20.34,31.877 21.073,31.877
  other v4: 28.448,33.528
5V_B: C23.1 U8.8 U11.1 | length 5.5
  Top Layer w0.381: U11.1@58.293,12.427 59.02,11.7 C23.1@60.046,11.7 60.468,11.7 62.09,13.322 U8.8@62.811,13.322
5V_T: C10.1 U7.8 U9.1 | length 2.1
  Bottom Layer w0.61: U9.1@60.96,31.153 61.795,31.988 C10.1@62.713,31.988
  other v2: 62.822,31.994
12V: J1.9 R10.1 | length 5.2
  Bottom Layer w1.27: R10.1@65.737,11.481 66.802,10.416 J1.9@66.802,6.731
AGND: C2.2 C3.2 C6.2 C14.1 C33.2 C35.2 C40.2 J1.2 J1.7 J1.11 J1.12 pad.1@68.326,33.604 U2.3 U2.4 U4.3 U4.4 U5.4 U5.6 U6.4 U6.6 U7.3 U7.4 U8.3 U8.4 | length 11.8
  Top Layer w0.381: v3(34.752,31.047) 34.822,31.117 C14.1@34.822,33.782 ; v2(38.887,34.639) 38.887,33.642 C2.2@39.167,33.363
  Top Layer w0.635: J1.12@69.342,4.191 J1.11@69.342,6.731
  Bottom Layer w0.381: v2(65.611,33.401) 67.132,33.401 67.158,33.426 ; 69.614,37.404 v2(73.182,37.404)
  other v1: 59.182,0.86 60.275,0.86 61.367,0.86 62.459,0.86 75.188,8.231 75.188,9.323 75.188,10.415 75.188,11.508 75.268,18.58 75.268,19.672 75.268,20.765 75.268,21.857 75.268,29.557 75.268,30.65 75.268,31.742 75.268,32.834 75.255,39.568 75.255,40.66 75.255,41.752 75.255,42.844
  other v2: 65.608,14.58 69.063,30.877 73.182,34.671 73.182,40.549
  other v3: 33.482,31.047 16.454,31.763 17.724,31.763
  other v4: 25.4,33.528
Bot_FET_FAULT: J1.3 U8.2 | length 14.9
  Top Layer w0.254: J1.3@59.182,6.731 60.503,8.052 66.167,8.052 67.234,9.119 67.234,12.954 66.366,13.822 U8.2@65.611,13.822
Bot_FET_FLT: CdrvB.2 RdrvB.2 U3.5 U8.7 | length 29.4
  Top Layer w0.254: v2(61.976,13.97) 62,13.946 62.306,13.946 62.431,13.822 U8.7@62.811,13.822
  Top Layer w0.508: U3.5@39.778,18.315 42.099,18.315 RdrvB.2@42.792,19.007 ; RdrvB.2@42.784,19.015 42.784,19.115 RdrvB.2@42.83,19.161 ; RdrvB.2@43.084,18.981 43.806,19.703 43.806,21.182 43.501,21.487 43.401,21.487 43.355,21.533 v2(43.355,21.633)
  Signal Layer 2 w0.381: v2(43.355,21.633) 54.313,21.633 v2(61.976,13.97) v2@61.988,13.958
Bot_FET_PWM: J1.1 pad.1@72.568,3.937 R16.1 | length 85.6
  Top Layer w0.254: v2(37.222,36.093) 40.259,36.093 48.374,27.978 52.261,27.978 52.857,27.381 69.901,27.381 74.397,22.885 74.397,5.791 70.18,1.575 56.642,1.575 55.143,3.073 55.143,5.232 J1.1@56.642,6.731
HVBUS: C5.2 C7.2 C8.2 C17.1 C19.1 C20.1 C21.1 C38.1 C66.2 HV.1 pad.1@13.462,7.214 pad.1@17.272,7.214 TP5.1 U1.9
  other v1: 9.388,2.071 10.023,2.071 10.658,2.071 11.293,2.071 11.928,2.071 12.563,2.071 13.198,2.071 13.833,2.071 14.468,2.071 15.103,2.071 15.738,2.071 16.373,2.071 17.008,2.071 17.643,2.071 9.706,2.617 10.341,2.617 10.976,2.617 11.611,2.617 12.246,2.617 12.881,2.617 13.516,2.617 14.151,2.617 14.786,2.617 15.421,2.617 16.056,2.617 16.691,2.617 17.326,2.617 9.388,3.163 10.023,3.163 10.658,3.163 11.293,3.163 11.928,3.163 12.563,3.163 13.198,3.163 13.833,3.163 14.468,3.163 15.103,3.163 15.738,3.163 16.373,3.163 17.008,3.163 17.643,3.163 9.52,13.791 10.155,13.791 9.838,14.337 9.695,16.252 9.377,16.798 10.012,16.798 1.119,18.017 1.754,18.017 1.436,18.563 1.119,19.109 1.754,19.109 1.436,19.656 1.119,20.202 1.754,20.202 1.436,20.748 9.733,21.001 1.119,21.294 1.754,21.294 9.416,21.547 10.051,21.547 1.436,21.84 1.119,22.386 1.754,22.386 1.436,22.932 1.119,23.478 1.754,23.478 1.436,24.024 1.119,24.57 1.754,24.57
IN_H: CgT.2 CrcT.2 D4.2 RssT.2 U1.8
IN_L: CgB.2 CrcB.2 D8.2 RssB.2 U3.8
ISO_12V_H: C9.1 C30.1 L3.2 R1.1 U9.2 | length 28.9
  Top Layer w0.508: L3.2@48.078,40.282 48.593,40.282 48.89,40.58 48.89,42.496
  Top Layer w0.61: 50.381,42.496 50.51,42.626 51.902,42.626 51.978,42.55 51.978,42.442 54.911,39.509 54.911,36.509 59.06,32.36 v2(59.06,31.153)
  Top Layer w0.762: 48.895,42.496 50.381,42.496
  Top Layer w1.27: R1.1@43.05,40.87 43.05,41.035 44.256,42.241 C30.1@45.125,42.241 ; C30.1@45.243,42.241 48.89,42.241
  Bottom Layer w0.61: C9.1@57.226,31.988 58.225,31.988 v2(59.06,31.153)
ISO_12V_H_B: C36.1 D3.1 L3.3
  other v2: 50.209,39.8
ISO_12V_L: C11.2 C22.1 C31.1 C41.1 L4.2 R2.1 R4.1 R10.2 U4.5 U11.2 | length 91
  Top Layer w0.254: R2.1@12.749,30.962 12.773,30.986 v2(13.803,30.986)
  Top Layer w0.508: v2(47.549,23.343) 47.549,21.198 C41.1@47.894,20.853 47.917,20.83 C31.1@47.917,19.075 47.917,17.933 47.992,17.859 47.992,17.71 48.14,17.71 48.215,17.635 48.285,17.635 48.393,17.527 L4.2@48.393,17.46 48.393,17.393 48.339,17.339 48.138,17.339 48.084,17.285 48.024,17.285 47.219,16.48 47.219,13.894 49.413,11.7 C22.1@54.559,11.7 55.666,11.7 U11.2@56.393,12.427 ; v2@47.627,23.343 C11.2@47.627,25.527
  Top Layer w0.635: v3@33.482,24.552 U4.5@33.482,25.883 ; v3(33.523,24.51) 34.106,23.927 R4.1@35.039,23.927
  Signal Layer 2 w0.635: v2(13.803,30.986) 13.803,30.42 14.542,29.682 30.019,29.682 33.523,26.178 v3(33.523,24.51) 34.691,23.343 v2(47.549,23.343)
  Bottom Layer w0.762: 47.398,23.081 47.398,14.095 50.013,11.481 R10.2@62.837,11.481
ISO_12V_L_B: C37.1 D2.1 L4.3
  other v2: 53.01,13.919 48.539,15.316 52.572,15.974
ISO_RET_H_B: C36.2 D3.2 L3.4
  other v2: 50.246,41.627
ISO_RET_L_B: C37.2 D2.2 L4.4
  other v2: 54.61,13.919 49.327,15.545 54.972,15.974
ISONC2: T2.5
ISONC3: T1.5
NC: U7.6
NC1: 
NC2: 
NC3: 
NC4: 
NetC4_2_1: C4_2.1 R3.2 U1.6 | length 9.1
  Top Layer w0.381: v3(19.444,24.054) 20.955,24.054 21.412,23.597 21.412,19.964 21.862,19.515 U1.6@22.711,19.515 22.837,19.388 C4_2.1@24.506,19.388
NetC13_2_1: C13_2.1 R4.2 U3.6 | length 8.9
  Top Layer w0.381: R4.2@36.639,23.927 37.922,23.927 38.43,23.419 38.43,23.148 38.449,23.129 38.449,19.819 38.753,19.515 U3.6@39.778,19.515
  Top Layer w0.508: U3.6@39.778,19.515 39.869,19.425 C13_2.1@41.573,19.425
NetCdrvB_1: CdrvB.1 RdrvB2.2 | length 1
  Top Layer w0.762: RdrvB2.2@42.248,22.833 CdrvB.1@43.208,22.833
NetCdrvT_1: CdrvT.1 RdrvT2.2 | length 0.9
  Top Layer w0.787: RdrvT2.2@25.197,22.833 CdrvT.1@26.137,22.833
NetCgB_1: CgB.1 RoffB.2 RonB.2 | length 4.8
  Top Layer w0.508: CgB.1@40.926,24.909 40.926,25.009 41.69,25.773 41.69,25.841 42.164,26.314 RonB.2@42.164,26.732 ; RonB.2@42.179,26.746 42.939,26.746 43.665,27.472 43.665,27.546 43.912,27.794 43.912,27.894 43.958,27.94 RoffB.2@44.058,27.94
NetCgT_1: CgT.1 RoffT.2 RonT.2 | length 4.9
  Top Layer w0.508: CgT.1@23.724,24.933 23.724,25.033 23.833,25.143 23.925,25.143 25.096,26.314 RonT.2@25.096,26.731 ; RonT.2@25.111,26.746 25.872,26.746 26.597,27.472 26.597,27.546 26.845,27.794 26.845,27.894 26.891,27.94 RoffT.2@26.991,27.94
NetD1_2: D1.2 R2.2 | length 3.9
  Top Layer w1.27: R2.2@12.749,33.862 12.994,33.862 13.009,33.877 13.009,37.068 13.114,37.173 D1.2@13.114,37.512
NetD2_3: D2.3 T2.4 | length 2.7
  Top Layer w0.508: D2.3@54.972,21.974 57.019,21.974 T2.4@57.448,22.403
NetD2_4: D2.4 T2.6 | length 7.1
  Top Layer w0.508: D2.4@52.572,21.974 52.572,21.545 56.794,17.323 T2.6@57.448,17.323
NetD3_3: D3.3 T1.4
  other v2: 57.448,41.504
NetD3_4: D3.4 T1.6 | length 3.5
  Bottom Layer w0.762: D3.4@57.099,39.776 57.099,36.773 v2(57.448,36.424)
NetD4_1: D4.1 D7.1 | length 1.2
  Top Layer w0.381: D4.1@26.286,25.504 26.286,25.554 26.761,26.029 D7.1@27.277,26.029
NetD8_1: D8.1 D9.1 | length 1.2
  Top Layer w0.381: D8.1@43.353,25.504 43.353,25.554 43.828,26.029 D9.1@44.345,26.029
NetDoffB_1: DoffB.1 RonB1.1 U4.6 U4.7
NetDoffB_2: DoffB.2 RoffB.1 | length 1.1
  Top Layer w0.635: DoffB.2@41.794,27.94 RoffB.1@42.858,27.94
NetDoffT_1: DoffT.1 RonT1.1 U2.6 U2.7
NetDoffT_2: DoffT.2 RoffT.1 | length 1.1
  Top Layer w0.635: DoffT.2@24.726,27.94 RoffT.1@25.791,27.94
NetR19_1: R19.1 U7.2 | length 2.9
  Top Layer w0.254: U7.2@65.611,32.643 66.026,32.643 R19.1@67.793,30.877
NetRonB1_2: RonB1.2 RonB.1 RssB.1
NetRonT1_2: RonT1.2 RonT.1 RssT.1
NetT1_1: T1.1 U6.3 | length 2.6
  Top Layer w0.508: T1.1@68.688,36.424 70.278,38.014 U6.3@70.582,38.014
NetT1_3: T1.3 U6.1 | length 2.6
  Top Layer w0.508: T1.3@68.688,41.504 68.992,41.504 U6.1@70.582,39.914
NetT2_1: T2.1 U5.3 | length 2.6
  Top Layer w0.508: T2.1@68.688,17.323 68.992,17.323 U5.3@70.582,18.913
NetT2_3: T2.3 U5.1 | length 2.6
  Top Layer w0.508: T2.3@68.688,22.403 70.278,20.813 U5.1@70.582,20.813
